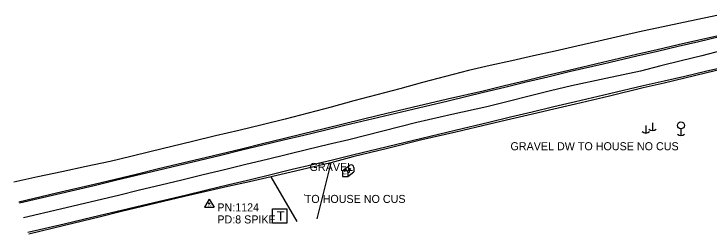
# Model space of a CAD drawing. Extents: x 1568433 to 1572450, y 731863 to 733450.
# Drawn here: x 1568611.3 to 1569044.4, y 731862.7 to 731999.7 of the extents above; entities that cross this region are included whole.
import ezdxf

# ---------------------------------------------------------------- set-up
doc = ezdxf.new("R2010")
doc.units = 0
for name, color, linetype in [('S_DITCHLINE', 7, 'Continuous'), ('S_DRIVEWAY', 7, 'Continuous'), ('S_DRIVEWAY_ANNOT', 7, 'Continuous'), ('S_EDGE_PAVEMENT', 7, 'Continuous'), ('S_MAILBOX', 7, 'Continuous'), ('S_MSC_PT_SYM', 7, 'Continuous'), ('S_PAVEMENT_CROWN', 7, 'Continuous'), ('S_SECONDARY_CTL', 7, 'Continuous'), ('S_SECONDARY_CTL_ANNOT', 7, 'Continuous'), ('S_SHOULDER', 7, 'Continuous'), ('S_SURVEY_TEXT_ANNOT', 7, 'Continuous'), ('S_TELEPHONE_UTILITIES', 7, 'Continuous'), ('S_UTILITY_POLE', 7, 'Continuous')]:
    doc.layers.add(name, color=color, linetype=linetype)

msp = doc.modelspace()

# ---------------------------------------------------------------- linework, layer by layer
at = {"layer": 'S_DITCHLINE'}
msp.add_lwpolyline([(1569054.1, 731999.69), (1569041.3, 731996.99), (1569028.51, 731994.28), (1569015.72, 731991.58), (1569002.93, 731988.88), (1568989.3, 731985.8), (1568975.67, 731982.73), (1568962.05, 731979.66), (1568948.42, 731976.58), (1568934.94, 731973.57), (1568921.45, 731970.56), (1568907.96, 731967.55), (1568894.48, 731964.54), (1568880.21, 731960.74), (1568865.94, 731956.93), (1568851.67, 731953.13), (1568837.4, 731949.33), (1568823.13, 731945.53), (1568808.86, 731941.73), (1568794.59, 731937.92), (1568780.32, 731934.12), (1568765.88, 731930.66), (1568751.43, 731927.21), (1568736.98, 731923.75), (1568722.53, 731920.29), (1568709.71, 731917.19), (1568696.88, 731914.09), (1568684.06, 731910.98), (1568671.23, 731907.88), (1568656.26, 731904.69), (1568641.28, 731901.49), (1568626.3, 731898.3), (1568611.32, 731895.1)], dxfattribs=at)
at = {"layer": 'S_DRIVEWAY'}
for points in [[(1568808.78, 731906.98), (1568804.41, 731889.64), (1568800.04, 731872.31)], [(1568787.86, 731870.61), (1568779.72, 731884.46), (1568771.58, 731898.31)]]:
    msp.add_lwpolyline(points, dxfattribs=at)
at = {"layer": 'S_EDGE_PAVEMENT'}
for points in [[(1569050.96, 731985.36), (1569038.07, 731982.36), (1569025.18, 731979.35), (1569012.28, 731976.35), (1568999.39, 731973.34), (1568978.34, 731968.45), (1568957.29, 731963.56), (1568943.91, 731960.36), (1568930.53, 731957.17), (1568917.16, 731953.97), (1568903.78, 731950.78), (1568881.8, 731945.51), (1568859.82, 731940.24), (1568838.66, 731935.22), (1568817.5, 731930.2), (1568804.75, 731927.15), (1568791.99, 731924.1), (1568779.24, 731921.06), (1568766.49, 731918.01), (1568753.38, 731914.84), (1568740.28, 731911.67), (1568727.17, 731908.5), (1568714.06, 731905.33), (1568700.9, 731902.21), (1568687.74, 731899.09), (1568674.57, 731895.96), (1568661.41, 731892.84), (1568638.12, 731887.35), (1568614.84, 731881.87)], [(1569055.13, 731966.76), (1569042.19, 731963.8), (1569029.25, 731960.83), (1569016.31, 731957.86), (1569003.37, 731954.89), (1568982.31, 731949.97), (1568961.25, 731945.05), (1568947.72, 731941.83), (1568934.2, 731938.61), (1568920.67, 731935.39), (1568907.15, 731932.17), (1568886.31, 731927.14), (1568865.48, 731922.11), (1568843.86, 731916.92), (1568822.24, 731911.74), (1568809.75, 731908.76), (1568797.25, 731905.79), (1568784.76, 731902.82), (1568772.26, 731899.84), (1568758.69, 731896.56), (1568745.12, 731893.28), (1568731.55, 731890.01), (1568717.98, 731886.73), (1568704.75, 731883.6), (1568691.53, 731880.47), (1568678.31, 731877.34), (1568665.08, 731874.21), (1568642.58, 731868.91), (1568620.08, 731863.61)]]:
    msp.add_lwpolyline(points, dxfattribs=at)
at = {"layer": 'S_MAILBOX'}
for p, q in [((1568816.47, 731902.54), (1568820.6, 731905.65)), ((1568820.09, 731903.83), (1568820.09, 731901.11)), ((1568823.04, 731904.17), (1568823.04, 731901.46)), ((1568815.92, 731901.26), (1568815.92, 731898.55)), ((1568815.92, 731898.55), (1568819.24, 731898.55)), ((1568819.24, 731898.55), (1568823.04, 731901.46)), ((1568819.24, 731901.26), (1568819.24, 731898.55))]:
    msp.add_line(p, q, dxfattribs=at)
for points in [[(1568820.09, 731903.83), (1568821.19, 731903.16), (1568820.09, 731902.81)], [(1568817.1, 731902.38), (1568817.32, 731902.24), (1568817.32, 731901.85), (1568817.63, 731901.85), (1568817.63, 731902.21), (1568817.43, 731902.46), (1568817.1, 731902.41)]]:
    msp.add_lwpolyline(points, dxfattribs=at)
for centre, end in [((1568817.58, 731901.26), 180), ((1568821.37, 731904.17), 117.5718)]:
    msp.add_arc(centre, 1.66, 0, end, dxfattribs=at)
msp.add_ellipse((1568820.09, 731901.11), major_axis=(0.145, 0.132), ratio=0.564646, dxfattribs=at)
at = {"layer": 'S_MSC_PT_SYM'}
for points in [[(1568920.66, 731919.87), (1568920.66, 731919.92), (1568920.66, 731919.87), (1568920.61, 731919.87), (1568920.66, 731919.87), (1568920.66, 731919.82), (1568920.66, 731919.87), (1568920.71, 731919.87)], [(1568792.5, 731887.09), (1568792.5, 731887.14), (1568792.5, 731887.09), (1568792.45, 731887.09), (1568792.5, 731887.09), (1568792.5, 731887.04), (1568792.5, 731887.09), (1568792.55, 731887.09)]]:
    msp.add_lwpolyline(points, dxfattribs=at)
at = {"layer": 'S_PAVEMENT_CROWN'}
msp.add_lwpolyline([(1569052.57, 731976.85), (1569039.82, 731973.68), (1569027.08, 731970.51), (1569014.33, 731967.34), (1569001.59, 731964.17), (1568980.16, 731959.59), (1568958.73, 731955.02), (1568945.54, 731951.75), (1568932.36, 731948.48), (1568919.17, 731945.21), (1568905.99, 731941.95), (1568884.12, 731937.02), (1568862.25, 731932.08), (1568841.12, 731926.74), (1568819.99, 731921.4), (1568807.24, 731918.35), (1568794.49, 731915.31), (1568781.74, 731912.26), (1568768.99, 731909.21), (1568755.72, 731905.98), (1568742.45, 731902.74), (1568729.18, 731899.51), (1568715.91, 731896.27), (1568702.75, 731893.11), (1568689.59, 731889.96), (1568676.43, 731886.8), (1568663.27, 731883.65), (1568640.34, 731878.19), (1568617.4, 731872.73)], dxfattribs=at)
at = {"layer": 'S_SECONDARY_CTL'}
for p, q in [((1568733.03, 731884.45), (1568730.02, 731879.5)), ((1568733.03, 731884.45), (1568735.98, 731879.5)), ((1568730.02, 731879.5), (1568735.98, 731879.5))]:
    msp.add_line(p, q, dxfattribs=at)
for radius in [0.311, 0.183, 0.103]:
    msp.add_circle((1568733.03, 731881.84), radius, dxfattribs=at)
at = {"layer": 'S_SHOULDER'}
for points in [[(1569051.04, 731986.28), (1569038.05, 731983.33), (1569025.07, 731980.37), (1569012.08, 731977.41), (1568999.09, 731974.46), (1568978.02, 731969.5), (1568956.95, 731964.54), (1568943.6, 731961.33), (1568930.25, 731958.13), (1568916.91, 731954.92), (1568903.56, 731951.71), (1568881.49, 731946.63), (1568859.42, 731941.56), (1568838.35, 731936.48), (1568817.28, 731931.41), (1568804.51, 731928.25), (1568791.74, 731925.1), (1568778.97, 731921.94), (1568766.2, 731918.79), (1568753.09, 731915.62), (1568739.97, 731912.46), (1568726.86, 731909.3), (1568713.74, 731906.13), (1568700.65, 731903.01), (1568687.57, 731899.88), (1568674.48, 731896.75), (1568661.39, 731893.62), (1568637.9, 731888.14), (1568614.42, 731882.66)], [(1569055.13, 731965.85), (1569042.2, 731962.81), (1569029.27, 731959.76), (1569016.34, 731956.71), (1569003.41, 731953.67), (1568982.25, 731948.57), (1568961.08, 731943.47), (1568947.7, 731940.36), (1568934.32, 731937.24), (1568920.93, 731934.13), (1568907.55, 731931.01), (1568886.55, 731926.19), (1568865.54, 731921.36), (1568844.01, 731916.05), (1568822.48, 731910.74), (1568808.78, 731906.98), (1568790.18, 731902.65), (1568771.58, 731898.31), (1568758.1, 731895.28), (1568744.62, 731892.26), (1568731.14, 731889.23), (1568717.66, 731886.2), (1568704.55, 731883.03), (1568691.44, 731879.85), (1568678.33, 731876.67), (1568665.22, 731873.49), (1568642.9, 731868.11), (1568620.59, 731862.72)]]:
    msp.add_lwpolyline(points, dxfattribs=at)
at = {"layer": 'S_TELEPHONE_UTILITIES'}
msp.add_lwpolyline([(1568772.44, 731869.47), (1568772.44, 731878.47), (1568781.44, 731878.47), (1568781.44, 731869.47)], close=True, dxfattribs=at)
at = {"layer": 'S_UTILITY_POLE'}
for p, q in [((1569004.89, 731930.29), (1569004.89, 731925.56)), ((1569009.09, 731931.84), (1569009.09, 731927.11)), ((1569026.88, 731928.18), (1569026.88, 731923.95))]:
    msp.add_line(p, q, dxfattribs=at)
msp.add_circle((1569026.87, 731930.36), 2.13, dxfattribs=at)
for centre, radius in [((1569004.95, 731928.99), 3.41), ((1569009.15, 731930.54), 3.41), ((1569026.88, 731927.06), 3.09)]:
    msp.add_arc(centre, radius, 226.3972, 313.6028, dxfattribs=at)

# ---------------------------------------------------------------- texts
at = {"layer": 'S_DRIVEWAY_ANNOT'}
msp.add_text('GRAVEL', height=5, dxfattribs=at).set_placement((1568795.51, 731901.98))
at = {"layer": 'S_MAILBOX'}
msp.add_text('US', height=0.96, rotation=360, dxfattribs=at).set_placement((1568816.68, 731899.74))
at = {"layer": 'S_SECONDARY_CTL'}
msp.add_text('TV', height=1.5, rotation=360, dxfattribs=at).set_placement((1568731.83, 731879.83))
at = {"layer": 'S_SECONDARY_CTL_ANNOT'}
for s, p in [('PN:1124', (1568738.03, 731876.84)), ('PD:8 SPIKE', (1568738.03, 731869.34))]:
    msp.add_text(s, height=5, dxfattribs=at).set_placement(p)
at = {"layer": 'S_SURVEY_TEXT_ANNOT'}
for s, p in [('GRAVEL DW TO HOUSE NO CUS', (1568920.66, 731914.87)), ('TO HOUSE NO CUS', (1568792.5, 731882.09))]:
    msp.add_text(s, height=5, dxfattribs=at).set_placement(p)
at = {"layer": 'S_TELEPHONE_UTILITIES'}
msp.add_text('T', height=6, rotation=360, dxfattribs=at).set_placement((1568775.01, 731870.97))

doc.saveas('drawing.dxf')
